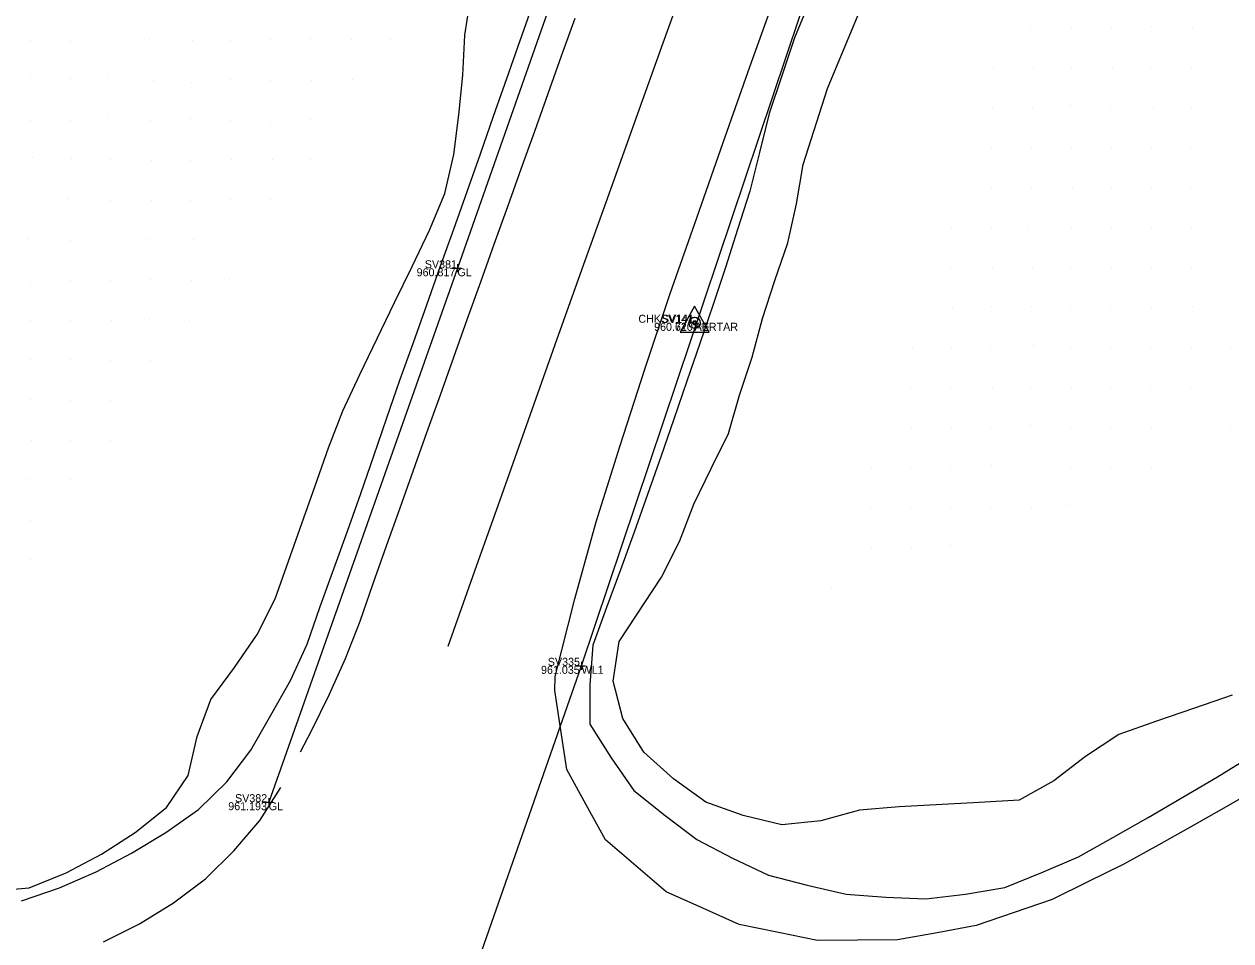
# Model space of a CAD drawing. Extents: x 2262025 to 2264532, y 740981 to 742724.
# Drawn here: x 2263077.7 to 2263228.5, y 741794.3 to 741908.8 of the extents above; entities that cross this region are included whole.
import ezdxf

# ---------------------------------------------------------------- set-up
doc = ezdxf.new("R2010")
doc.units = 0
for name, color, linetype in [('GE_X_Alignment_100_Curve_Data', 7, 'Continuous'), ('Ground Shots', 7, 'Continuous'), ('HY_X_Spring_Cells', 7, 'Continuous'), ('RW_X_CL', 7, 'Continuous'), ('RW_X_CL_1000_Bearings', 7, 'Continuous'), ('RW_X_CL_1000_Distances', 7, 'Continuous'), ('RW_X_CL_1000_Stations', 7, 'Continuous'), ('RW_X_CL_100_Cardinal_Points', 7, 'Continuous'), ('SC_Scratch4', 7, 'Continuous'), ('SV_X_Control_Cells_Found', 7, 'Continuous'), ('SV_X_Text_Comment', 7, 'Continuous'), ('UT_X_Gas', 7, 'Continuous'), ('UT_X_Water', 7, 'Continuous')]:
    doc.layers.add(name, color=color, linetype=linetype)

msp = doc.modelspace()

# ---------------------------------------------------------------- linework, layer by layer
at = {"layer": 'GE_X_Alignment_100_Curve_Data'}
for points in [[(2263077.39, 741799.28), (2263082.11, 741800.93), (2263086.69, 741802.93), (2263091.1, 741805.26), (2263095.39, 741807.83), (2263099.48, 741810.71), (2263103.05, 741814.17), (2263106.03, 741818.14), (2263108.51, 741822.49), (2263110.99, 741826.83), (2263113.06, 741831.35), (2263114.69, 741836.08), (2263116.42, 741840.77), (2263118.12, 741845.47), (2263119.76, 741850.2), (2263121.39, 741854.92), (2263123.03, 741859.65), (2263124.66, 741864.37), (2263126.34, 741869.08), (2263128.02, 741873.79), (2263129.7, 741878.5), (2263131.38, 741883.21), (2263133.06, 741887.92), (2263134.72, 741892.64), (2263136.37, 741897.35), (2263138.03, 741902.07), (2263139.68, 741906.79), (2263141.34, 741911.51)], [(2263175.86, 741911.77), (2263173.98, 741907.14), (2263172.38, 741902.4), (2263170.79, 741897.66), (2263169.58, 741892.81), (2263168.37, 741887.96), (2263166.85, 741883.19), (2263165.34, 741878.43), (2263163.74, 741873.69), (2263162.15, 741868.95), (2263160.52, 741864.22), (2263158.89, 741859.49), (2263157.24, 741854.77), (2263155.59, 741850.05), (2263153.91, 741845.35), (2263152.23, 741840.64), (2263150.49, 741835.95), (2263148.76, 741831.26), (2263148.38, 741826.27), (2263148.38, 741821.39), (2263151.05, 741817.16), (2263153.89, 741813.09), (2263157.79, 741809.96), (2263161.77, 741806.95), (2263166.2, 741804.64), (2263170.7, 741802.49), (2263175.54, 741801.24), (2263180.4, 741800.13), (2263185.39, 741799.75), (2263190.37, 741799.53), (2263195.34, 741800.13), (2263200.24, 741800.94), (2263204.87, 741802.82), (2263209.46, 741804.81), (2263213.82, 741807.26), (2263218.17, 741809.72), (2263222.49, 741812.24), (2263226.8, 741814.77), (2263231.05, 741817.4)]]:
    msp.add_lwpolyline(points, dxfattribs=at)
at = {"layer": 'Ground Shots'}
for p, q in [((2263203.48, 741908.49), (2263203.48, 741908.49)), ((2263208.53, 741908.41), (2263208.53, 741908.41)), ((2263213.53, 741908.43), (2263213.53, 741908.43)), ((2263218.53, 741908.5), (2263218.53, 741908.5)), ((2263223.74, 741908.38), (2263223.74, 741908.38)), ((2263078.5, 741906.82), (2263078.5, 741906.82)), ((2263083.46, 741906.66), (2263083.46, 741906.66)), ((2263088.36, 741906.61), (2263088.36, 741906.61)), ((2263093.41, 741906.95), (2263093.41, 741906.95)), ((2263098.7, 741906.82), (2263098.7, 741906.82)), ((2263103.52, 741906.81), (2263103.52, 741906.81)), ((2263108.44, 741906.87), (2263108.44, 741906.87)), ((2263113.54, 741907), (2263113.54, 741907)), ((2263118.55, 741906.89), (2263118.55, 741906.89)), ((2263123.53, 741906.9), (2263123.53, 741906.9)), ((2263078.47, 741902.15), (2263078.47, 741902.15)), ((2263088.24, 741902.13), (2263088.24, 741902.13)), ((2263198.8, 741903.31), (2263198.8, 741903.31)), ((2263203.85, 741903.4), (2263203.85, 741903.4)), ((2263208.56, 741903.35), (2263208.56, 741903.35)), ((2263213.65, 741903.45), (2263213.65, 741903.45)), ((2263218.48, 741903.39), (2263218.48, 741903.39)), ((2263223.59, 741903.25), (2263223.59, 741903.25)), ((2263083.48, 741902.02), (2263083.48, 741902.02)), ((2263093.89, 741901.78), (2263093.89, 741901.78)), ((2263098.66, 741901.61), (2263098.66, 741901.61)), ((2263103.43, 741901.87), (2263103.43, 741901.87)), ((2263108.53, 741901.85), (2263108.53, 741901.85)), ((2263113.55, 741901.8), (2263113.55, 741901.8)), ((2263118.71, 741901.87), (2263118.71, 741901.87)), ((2263198.71, 741898.34), (2263198.71, 741898.34)), ((2263203.65, 741898.37), (2263203.65, 741898.37)), ((2263208.5, 741898.67), (2263208.5, 741898.67)), ((2263213.45, 741898.52), (2263213.45, 741898.52)), ((2263218.76, 741898.36), (2263218.76, 741898.36)), ((2263223.6, 741898.37), (2263223.6, 741898.37)), ((2263078.54, 741896.8), (2263078.54, 741896.8)), ((2263083.51, 741896.75), (2263083.51, 741896.75)), ((2263088.09, 741897.17), (2263088.09, 741897.17)), ((2263093.54, 741896.84), (2263093.54, 741896.84)), ((2263098.54, 741897.08), (2263098.54, 741897.08)), ((2263103.48, 741896.76), (2263103.48, 741896.76)), ((2263108.47, 741896.61), (2263108.47, 741896.61)), ((2263113.5, 741896.89), (2263113.5, 741896.89)), ((2263198.54, 741893.46), (2263198.54, 741893.46)), ((2263203.62, 741893.49), (2263203.62, 741893.49)), ((2263208.52, 741893.39), (2263208.52, 741893.39)), ((2263213.63, 741893.42), (2263213.63, 741893.42)), ((2263218.57, 741893.34), (2263218.57, 741893.34)), ((2263223.46, 741893.39), (2263223.46, 741893.39)), ((2263078.74, 741892.18), (2263078.74, 741892.18)), ((2263083.64, 741892.06), (2263083.64, 741892.06)), ((2263088.44, 741891.95), (2263088.44, 741891.95)), ((2263093.59, 741891.84), (2263093.59, 741891.84)), ((2263098.43, 741891.83), (2263098.43, 741891.83)), ((2263103.57, 741891.92), (2263103.57, 741891.92)), ((2263108.78, 741891.89), (2263108.78, 741891.89)), ((2263113.45, 741891.91), (2263113.45, 741891.91)), ((2263083.29, 741887.05), (2263083.29, 741887.05)), ((2263193.96, 741888.12), (2263193.96, 741888.12)), ((2263198.53, 741888.42), (2263198.53, 741888.42)), ((2263203.52, 741888.37), (2263203.52, 741888.37)), ((2263208.68, 741888.34), (2263208.68, 741888.34)), ((2263213.58, 741888.38), (2263213.58, 741888.38)), ((2263218.54, 741888.46), (2263218.54, 741888.46)), ((2263223.48, 741888.42), (2263223.48, 741888.42)), ((2263088.47, 741886.81), (2263088.47, 741886.81)), ((2263093.65, 741886.84), (2263093.65, 741886.84)), ((2263098.53, 741886.82), (2263098.53, 741886.82)), ((2263103.5, 741886.89), (2263103.5, 741886.89)), ((2263108.5, 741886.89), (2263108.5, 741886.89)), ((2263193.63, 741883.49), (2263193.63, 741883.49)), ((2263198.57, 741883.38), (2263198.57, 741883.38)), ((2263203.24, 741883.59), (2263203.24, 741883.59)), ((2263208.57, 741883.37), (2263208.57, 741883.37)), ((2263213.58, 741883.45), (2263213.58, 741883.45)), ((2263218.52, 741883.4), (2263218.52, 741883.4)), ((2263223.58, 741883.47), (2263223.58, 741883.47)), ((2263078.23, 741882), (2263078.23, 741882)), ((2263083.44, 741881.86), (2263083.44, 741881.86)), ((2263088.36, 741882.19), (2263088.36, 741882.19)), ((2263093.37, 741882.02), (2263093.37, 741882.02)), ((2263098.88, 741881.96), (2263098.88, 741881.96)), ((2263193.46, 741878.39), (2263193.46, 741878.39)), ((2263198.66, 741878.46), (2263198.66, 741878.46)), ((2263203.74, 741878.48), (2263203.74, 741878.48)), ((2263208.49, 741878.45), (2263208.49, 741878.45)), ((2263213.51, 741878.47), (2263213.51, 741878.47)), ((2263218.51, 741878.41), (2263218.51, 741878.41)), ((2263223.52, 741878.48), (2263223.52, 741878.48)), ((2263078.53, 741876.58), (2263078.53, 741876.58)), ((2263083.56, 741876.83), (2263083.56, 741876.83)), ((2263088.52, 741876.83), (2263088.52, 741876.83)), ((2263093.46, 741876.89), (2263093.46, 741876.89)), ((2263098.58, 741876.82), (2263098.58, 741876.82)), ((2263103.31, 741876.96), (2263103.31, 741876.96)), ((2263198.56, 741873.51), (2263198.56, 741873.51)), ((2263203.58, 741873.57), (2263203.58, 741873.57)), ((2263208.5, 741873.52), (2263208.5, 741873.52)), ((2263213.48, 741873.5), (2263213.48, 741873.5)), ((2263218.63, 741873.45), (2263218.63, 741873.45)), ((2263223.72, 741873.55), (2263223.72, 741873.55)), ((2263093.41, 741871.92), (2263093.41, 741871.92)), ((2263193.74, 741873.36), (2263193.74, 741873.36)), ((2263078.45, 741871.85), (2263078.45, 741871.85)), ((2263083.54, 741871.81), (2263083.54, 741871.81)), ((2263088.56, 741871.87), (2263088.56, 741871.87)), ((2263098.34, 741871.85), (2263098.34, 741871.85)), ((2263188.67, 741868.38), (2263188.67, 741868.38)), ((2263193.53, 741868.46), (2263193.53, 741868.46)), ((2263198.5, 741868.52), (2263198.5, 741868.52)), ((2263203.86, 741868.68), (2263203.86, 741868.68)), ((2263208.5, 741868.49), (2263208.5, 741868.49)), ((2263213.5, 741868.47), (2263213.5, 741868.47)), ((2263218.47, 741868.41), (2263218.47, 741868.41)), ((2263223.58, 741868.43), (2263223.58, 741868.43)), ((2263228.42, 741868.47), (2263228.42, 741868.47)), ((2263078.51, 741866.9), (2263078.51, 741866.9)), ((2263083.54, 741866.89), (2263083.54, 741866.89)), ((2263088.54, 741866.78), (2263088.54, 741866.78)), ((2263093.55, 741866.86), (2263093.55, 741866.86)), ((2263188.5, 741863.4), (2263188.5, 741863.4)), ((2263193.5, 741863.42), (2263193.5, 741863.42)), ((2263198.65, 741863.32), (2263198.65, 741863.32)), ((2263203.47, 741863.42), (2263203.47, 741863.42)), ((2263208.54, 741863.44), (2263208.54, 741863.44)), ((2263213.48, 741863.4), (2263213.48, 741863.4)), ((2263218.5, 741863.51), (2263218.5, 741863.51)), ((2263223.41, 741863.44), (2263223.41, 741863.44)), ((2263228.36, 741863.45), (2263228.36, 741863.45)), ((2263078.52, 741861.94), (2263078.52, 741861.94)), ((2263083.55, 741861.85), (2263083.55, 741861.85)), ((2263088.54, 741861.85), (2263088.54, 741861.85)), ((2263188.56, 741858.47), (2263188.56, 741858.47)), ((2263193.59, 741858.37), (2263193.59, 741858.37)), ((2263198.48, 741858.4), (2263198.48, 741858.4)), ((2263203.41, 741858.72), (2263203.41, 741858.72)), ((2263208.46, 741858.43), (2263208.46, 741858.43)), ((2263213.48, 741858.41), (2263213.48, 741858.41)), ((2263218.51, 741858.37), (2263218.51, 741858.37)), ((2263228.41, 741858.56), (2263228.41, 741858.56)), ((2263078.61, 741856.82), (2263078.61, 741856.82)), ((2263083.54, 741856.83), (2263083.54, 741856.83)), ((2263088.54, 741856.87), (2263088.54, 741856.87)), ((2263183.57, 741853.44), (2263183.57, 741853.44)), ((2263188.51, 741853.46), (2263188.51, 741853.46)), ((2263193.49, 741853.52), (2263193.49, 741853.52)), ((2263198.59, 741853.66), (2263198.59, 741853.66)), ((2263203.35, 741853.41), (2263203.35, 741853.41)), ((2263208.5, 741853.38), (2263208.5, 741853.38)), ((2263213.46, 741853.46), (2263213.46, 741853.46)), ((2263218.53, 741853.44), (2263218.53, 741853.44)), ((2263078.32, 741852.08), (2263078.32, 741852.08)), ((2263083.54, 741851.92), (2263083.54, 741851.92)), ((2263183.45, 741848.44), (2263183.45, 741848.44)), ((2263188.5, 741848.41), (2263188.5, 741848.41)), ((2263193.49, 741848.43), (2263193.49, 741848.43)), ((2263198.51, 741848.47), (2263198.51, 741848.47)), ((2263203.58, 741848.41), (2263203.58, 741848.41)), ((2263208.34, 741848.74), (2263208.34, 741848.74)), ((2263078.5, 741846.86), (2263078.5, 741846.86)), ((2263183.55, 741843.4), (2263183.55, 741843.4)), ((2263188.53, 741843.36), (2263188.53, 741843.36)), ((2263193.4, 741843.66), (2263193.4, 741843.66)), ((2263078.46, 741841.91), (2263078.46, 741841.91)), ((2263178.63, 741838.47), (2263178.63, 741838.47))]:
    msp.add_line(p, q, dxfattribs=at)
at = {"layer": 'RW_X_CL_1000_Bearings'}
msp.add_line((2263161.48, 741871.52), (2263161.48, 741871.52), dxfattribs=at)
msp.add_line((2263161.48, 741871.52), (2263161.48, 741871.52), dxfattribs=at)
msp.add_line((2263161.48, 741871.52), (2263161.48, 741871.52), dxfattribs=at)
msp.add_lwpolyline([(2263159.68, 741870.37), (2263163.28, 741870.37), (2263161.48, 741873.59)], close=True, dxfattribs=at)
msp.add_lwpolyline([(2263159.68, 741870.37), (2263163.28, 741870.37), (2263161.48, 741873.59)], close=True, dxfattribs=at)
for centre, radius in [((2263161.48, 741871.53), 0.7), ((2263161.48, 741871.52), 0.7), ((2263161.48, 741871.53), 0.16), ((2263161.48, 741871.52), 0.16)]:
    msp.add_circle(centre, radius, dxfattribs=at)
at = {"layer": 'RW_X_CL_1000_Distances'}
for points in [[(2263144.07, 741827.33), (2263146.5, 741837.03), (2263149.17, 741846.66), (2263152.19, 741856.2), (2263155.25, 741865.72), (2263158.43, 741875.2), (2263161.74, 741884.64), (2263165.04, 741894.07), (2263168.4, 741903.49), (2263171.77, 741912.91), (2263175.14, 741922.32), (2263178.52, 741931.74), (2263181.9, 741941.15), (2263185.27, 741950.56), (2263188.61, 741959.99), (2263191.96, 741969.41), (2263195.3, 741978.83), (2263198.65, 741988.26), (2263202.01, 741997.67), (2263205.4, 742007.08), (2263208.8, 742016.49), (2263212.12, 742025.92), (2263215.45, 742035.35), (2263216.18, 742037.41)], [(2263146.5, 741909.55), (2263144.82, 741904.84), (2263143.14, 741900.14), (2263141.46, 741895.43), (2263139.77, 741890.72), (2263138.09, 741886.01), (2263136.41, 741881.3), (2263134.73, 741876.59), (2263133.04, 741871.88), (2263131.36, 741867.18), (2263129.68, 741862.47), (2263128, 741857.76), (2263126.32, 741853.05), (2263124.63, 741848.34), (2263122.95, 741843.63), (2263121.27, 741838.92), (2263119.63, 741834.2), (2263117.83, 741829.54), (2263115.77, 741824.99), (2263113.58, 741820.49), (2263112.18, 741817.87)], [(2263232.53, 741813.7), (2263228.19, 741811.22), (2263223.84, 741808.75), (2263219.48, 741806.31), (2263215.12, 741803.87), (2263210.63, 741801.66), (2263206.14, 741799.47), (2263201.41, 741797.83), (2263196.68, 741796.22), (2263191.77, 741795.31), (2263186.85, 741794.43), (2263181.85, 741794.37), (2263176.85, 741794.34), (2263171.95, 741795.32), (2263167.05, 741796.32), (2263162.49, 741798.36), (2263157.93, 741800.42), (2263154.13, 741803.67), (2263150.34, 741806.93), (2263147.92, 741811.3), (2263145.53, 741815.69), (2263144.76, 741820.63), (2263144.02, 741825.57), (2263144.07, 741827.33)], [(2263087.64, 741794.19), (2263092.11, 741796.42), (2263096.36, 741799.03), (2263100.37, 741802.03), (2263103.91, 741805.53), (2263107.16, 741809.32), (2263109.79, 741813.45)]]:
    msp.add_lwpolyline(points, dxfattribs=at)
at = {"layer": 'RW_X_CL_1000_Stations'}
msp.add_line((2263161.48, 741871.52), (2263161.48, 741871.52), dxfattribs=at)
msp.add_line((2263161.48, 741871.52), (2263161.48, 741871.52), dxfattribs=at)
msp.add_line((2263161.48, 741871.52), (2263161.48, 741871.52), dxfattribs=at)
msp.add_circle((2263161.48, 741871.52), 0.25, dxfattribs=at)
msp.add_circle((2263161.48, 741871.52), 0.25, dxfattribs=at)
msp.add_circle((2263161.48, 741871.52), 0.25, dxfattribs=at)
at = {"layer": 'RW_X_CL_100_Cardinal_Points'}
for p, q in [((2263131.35, 741878.34), (2263132.35, 741878.34)), ((2263131.85, 741878.84), (2263131.85, 741877.84)), ((2263131.85, 741878.34), (2263131.85, 741878.34)), ((2263146.86, 741828.66), (2263147.86, 741828.66)), ((2263147.36, 741829.16), (2263147.36, 741828.16)), ((2263147.36, 741828.66), (2263147.36, 741828.66)), ((2263107.76, 741811.62), (2263108.76, 741811.62)), ((2263108.26, 741812.12), (2263108.26, 741811.12)), ((2263108.26, 741811.62), (2263108.26, 741811.62))]:
    msp.add_line(p, q, dxfattribs=at)
at = {"layer": 'SC_Scratch4'}
msp.add_lwpolyline([(2263130.7, 741831.13), (2263134.04, 741840.55), (2263137.38, 741849.98), (2263140.73, 741859.4), (2263144.07, 741868.83), (2263147.42, 741878.25), (2263150.8, 741887.66), (2263154.17, 741897.08), (2263157.55, 741906.49), (2263160.93, 741915.9), (2263164.27, 741925.33), (2263167.6, 741934.75), (2263170.94, 741944.18), (2263174.28, 741953.61), (2263177.64, 741963.03), (2263181.03, 741972.43), (2263184.42, 741981.84), (2263187.82, 741991.25), (2263191.21, 742000.65), (2263194.57, 742010.07), (2263197.89, 742019.5), (2263201.21, 742028.94), (2263203.22, 742034.64)], dxfattribs=at)
at = {"layer": 'SV_X_Control_Cells_Found'}
for points in [[(2263073.42, 741800.48), (2263078.34, 741800.93), (2263082.97, 741802.81), (2263087.39, 741805.12), (2263091.58, 741807.85), (2263095.48, 741810.95), (2263098.21, 741814.95), (2263099.32, 741819.83), (2263101.04, 741824.44), (2263104, 741828.46), (2263106.83, 741832.58), (2263109.07, 741837.03), (2263110.74, 741841.74), (2263112.41, 741846.45), (2263114.08, 741851.16), (2263115.75, 741855.88), (2263117.54, 741860.54), (2263119.65, 741865.07), (2263121.82, 741869.57), (2263124, 741874.08), (2263126.18, 741878.58), (2263128.35, 741883.08), (2263130.27, 741887.68), (2263131.38, 741892.54), (2263132.02, 741897.5), (2263132.52, 741902.47), (2263132.76, 741907.45), (2263133.51, 741912.35)], [(2263228.66, 741824.98), (2263223.93, 741823.36), (2263219.2, 741821.74), (2263214.5, 741820.07), (2263210.33, 741817.31), (2263206.37, 741814.27), (2263202.02, 741811.89), (2263197.03, 741811.6), (2263187.04, 741811.02), (2263182.07, 741810.64), (2263177.26, 741809.27), (2263172.39, 741808.78), (2263167.53, 741809.95), (2263162.89, 741811.61), (2263158.84, 741814.54), (2263155.15, 741817.86), (2263152.51, 741822.07), (2263151.29, 741826.76), (2263152.04, 741831.7), (2263157.33, 741839.73), (2263159.58, 741844.18), (2263161.38, 741848.84), (2263163.55, 741853.3), (2263165.71, 741857.7), (2263167.09, 741862.49), (2263168.68, 741867.22), (2263169.98, 741872.05), (2263171.5, 741876.8), (2263173.14, 741881.52), (2263174.22, 741886.39), (2263175.04, 741891.32), (2263178.09, 741900.8), (2263181.93, 741910.02)]]:
    msp.add_lwpolyline(points, dxfattribs=at)
at = {"layer": 'UT_X_Gas'}
msp.add_lwpolyline([(2263370.65, 742558.56), (2263358.32, 742523.53), (2263332.75, 742449.83), (2263131.85, 741878.34), (2263108.26, 741811.62)], dxfattribs=at)
at = {"layer": 'UT_X_Water'}
msp.add_lwpolyline([(2263058.18, 741572.97), (2263085.82, 741651.25), (2263095.93, 741679.99), (2263097.95, 741685.82), (2263106.82, 741712.78), (2263147.36, 741828.66), (2263178.07, 741920.18), (2263217.98, 742032.49), (2263252.6, 742127.99), (2263295.63, 742247.6), (2263334.95, 742356.22), (2263370.78, 742449.55), (2263413.67, 742573.04), (2263421.38, 742593.43)], dxfattribs=at)

# ---------------------------------------------------------------- texts
at = {"layer": 'HY_X_Spring_Cells'}
for s, p in [('960.817', (2263126.75, 741877.34)), ('960.620', (2263156.42, 741870.52)), ('960.710', (2263156.42, 741870.53)), ('961.035', (2263142.29, 741827.66)), ('961.193', (2263103.21, 741810.62))]:
    msp.add_text(s, height=1, dxfattribs=at).set_placement(p)
at = {"layer": 'RW_X_CL'}
for s, p in [('GL', (2263131.85, 741877.34)), ('AERTAR', (2263161.48, 741870.53)), ('AERTAR', (2263161.48, 741870.52)), ('WL1', (2263147.36, 741827.66)), ('GL', (2263108.26, 741810.62))]:
    msp.add_text(s, height=1, dxfattribs=at).set_placement(p)
at = {"layer": 'RW_X_CL_1000_Stations'}
for s, p in [('ΔZ: 0.154', (2263161.48, 741870.82)), ('ΔZ: 0.154', (2263161.48, 741870.82)), ('ΔZ: 0.154', (2263161.48, 741870.82)), ('Index: 50', (2263161.48, 741871.22)), ('Index: 59', (2263161.48, 741871.22)), ('Index: 68', (2263161.48, 741871.22))]:
    msp.add_text(s, height=0.3, dxfattribs=at).set_placement(p)
at = {"layer": 'SV_X_Text_Comment'}
for s, p in [('SV381', (2263127.77, 741878.34)), ('CHKSV141', (2263154.45, 741871.53)), ('SV141', (2263157.4, 741871.52)), ('SV335', (2263143.14, 741828.66)), ('SV382', (2263104.06, 741811.62))]:
    msp.add_text(s, height=1, dxfattribs=at).set_placement(p)

doc.saveas('drawing.dxf')
